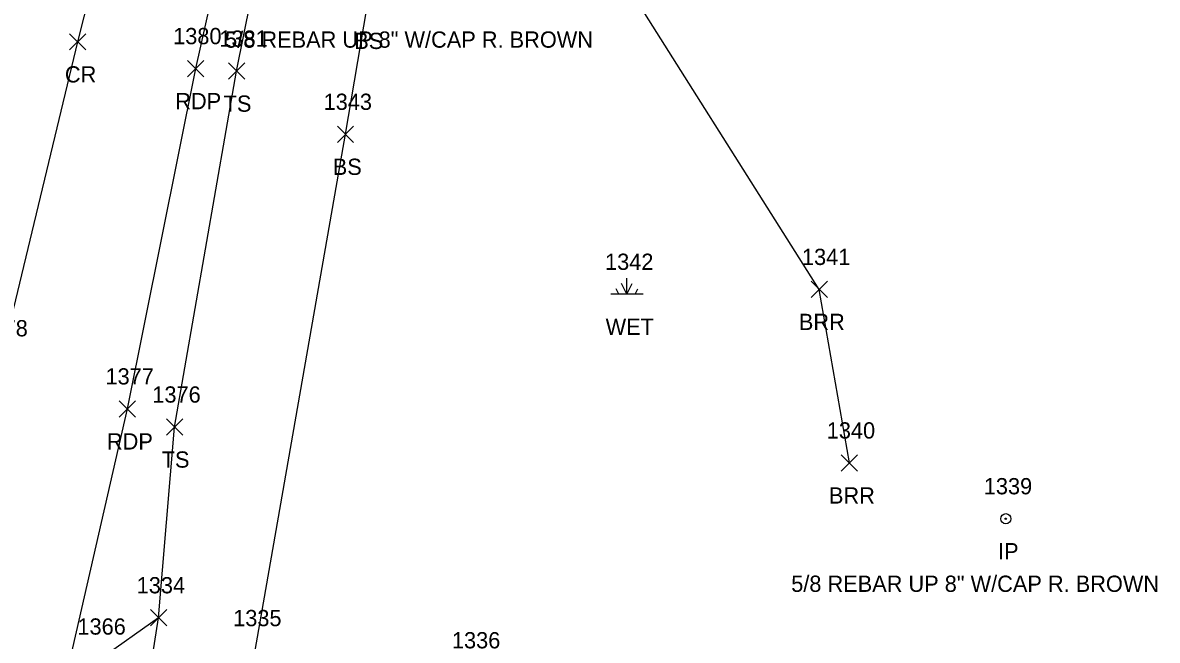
# Model space of a CAD drawing. Extents: x 1654425 to 1656893, y 667839 to 678429.
# Drawn here: x 1654625.8 to 1654765.3, y 668426.8 to 668502.8 of the extents above; entities that cross this region are included whole.
import ezdxf

# ---------------------------------------------------------------- set-up
doc = ezdxf.new("R2010")
doc.units = 0
for name, color, linetype in [('L_A', 7, 'Continuous'), ('L_I', 7, 'Continuous'), ('L_TIC', 7, 'Continuous'), ('LABL', 7, 'Continuous'), ('LELB', 7, 'Continuous'), ('LWET', 7, 'Continuous'), ('M_A', 7, 'Continuous'), ('M_C', 7, 'Continuous'), ('M_I', 7, 'Continuous'), ('MPIR', 7, 'Continuous'), ('P_A', 7, 'Continuous'), ('P_I', 7, 'Continuous'), ('P_TIC', 7, 'Continuous'), ('PET', 7, 'Continuous'), ('PRC', 7, 'Continuous'), ('R_I', 7, 'Continuous'), ('R_TIC', 7, 'Continuous'), ('RGR', 7, 'Continuous')]:
    doc.layers.add(name, color=color, linetype=linetype)

msp = doc.modelspace()

# ---------------------------------------------------------------- linework, layer by layer
at = {"layer": 'L_TIC'}
for points in [[(1654651.12, 668495.86), (1654653.12, 668497.86)], [(1654653.12, 668495.86), (1654651.12, 668497.86)], [(1654664.51, 668488.09), (1654666.51, 668490.09)], [(1654666.51, 668488.09), (1654664.51, 668490.09)], [(1654722.77, 668469.01), (1654724.77, 668471.01)], [(1654724.77, 668469.01), (1654722.77, 668471.01)], [(1654643.5, 668452.08), (1654645.5, 668454.08)], [(1654645.5, 668452.08), (1654643.5, 668454.08)], [(1654726.47, 668447.66), (1654728.47, 668449.66)], [(1654728.47, 668447.66), (1654726.47, 668449.66)], [(1654641.53, 668428.62), (1654643.53, 668430.62)], [(1654643.53, 668428.62), (1654641.53, 668430.62)]]:
    msp.add_lwpolyline(points, dxfattribs=at)
at = {"layer": 'LABL'}
msp.add_lwpolyline([(1654727.47, 668448.66), (1654723.77, 668470.01), (1654697.39, 668511.78), (1654690.89, 668526.25), (1654681.79, 668540.29), (1654676.53, 668550.52), (1654673.89, 668561.81), (1654676.18, 668560.69), (1654702.29, 668559.21), (1654719.79, 668550.09), (1654734.69, 668533.56)], dxfattribs=at)
at = {"layer": 'LELB'}
for points in [[(1654627.02, 668380.04), (1654635.38, 668394.96), (1654638.88, 668406.25), (1654642.53, 668429.62), (1654644.5, 668453.08), (1654652.12, 668496.86), (1654659.06, 668531.43), (1654666.85, 668565.91), (1654678.58, 668597.56)], [(1654632.09, 668378.26), (1654647.7, 668382.66), (1654658.31, 668401.62), (1654653.52, 668410.41), (1654654.39, 668425.58), (1654665.51, 668489.09), (1654668.15, 668504.58), (1654668.74, 668510.32), (1654667.06, 668546.44)]]:
    msp.add_lwpolyline(points, dxfattribs=at)
at = {"layer": 'LWET'}
for p, q in [((1654700.12, 668469.41), (1654699.45, 668470.74)), ((1654700.12, 668469.41), (1654700.12, 668471.41)), ((1654700.12, 668469.41), (1654700.78, 668470.74)), ((1654702.12, 668469.41), (1654698.12, 668469.41)), ((1654699.12, 668469.41), (1654698.78, 668470.08)), ((1654701.12, 668469.41), (1654701.45, 668470.08))]:
    msp.add_line(p, q, dxfattribs=at)
at = {"layer": 'MPIR'}
for radius in [0.625, 0.0833]:
    msp.add_circle((1654746.7, 668441.8), radius, dxfattribs=at)
at = {"layer": 'P_TIC'}
for points in [[(1654631.58, 668499.46), (1654633.58, 668501.46)], [(1654633.58, 668499.46), (1654631.58, 668501.46)], [(1654646.1, 668496.17), (1654648.1, 668498.17)], [(1654648.1, 668496.17), (1654646.1, 668498.17)], [(1654637.69, 668454.31), (1654639.69, 668456.31)], [(1654639.69, 668454.31), (1654637.69, 668456.31)]]:
    msp.add_lwpolyline(points, dxfattribs=at)
at = {"layer": 'PET'}
msp.add_lwpolyline([(1654621.12, 668380.08), (1654629.57, 668415.34), (1654638.69, 668455.31), (1654647.1, 668497.17), (1654655.08, 668532.73), (1654664.14, 668568.47), (1654670.36, 668590.98), (1654672.51, 668598), (1654685.45, 668641.36), (1654697.27, 668678.88), (1654709.65, 668714.91), (1654724.45, 668757.78), (1654737.22, 668795.28), (1654745.33, 668819.59), (1654761.32, 668866.34)], dxfattribs=at)
at = {"layer": 'PRC'}
msp.add_lwpolyline([(1654605.24, 668384.01), (1654612.68, 668416.68), (1654623.19, 668461.23), (1654632.58, 668500.46), (1654641.79, 668536.76), (1654650.75, 668570.78), (1654657.62, 668594.43), (1654672.71, 668645.31)], dxfattribs=at)
at = {"layer": 'R_TIC'}
for points in [[(1654641.53, 668428.62), (1654643.53, 668430.62)], [(1654643.53, 668428.62), (1654641.53, 668430.62)]]:
    msp.add_lwpolyline(points, dxfattribs=at)
at = {"layer": 'RGR'}
msp.add_lwpolyline([(1654642.53, 668429.62), (1654635.35, 668424.54), (1654632.73, 668419.18), (1654625.67, 668394.94), (1654622.06, 668380.67)], dxfattribs=at)

# ---------------------------------------------------------------- texts
at = {"layer": 'L_A'}
for s, p in [('BS', (1654666.59, 668499.58)), ('TS', (1654650.53, 668491.86)), ('BS', (1654663.95, 668484.09)), ('WET', (1654697.5, 668464.41)), ('BRR', (1654721.26, 668465.01)), ('TS', (1654642.91, 668448.08)), ('BRR', (1654724.96, 668443.66))]:
    msp.add_text(s, height=2, dxfattribs=at).set_placement(p)
at = {"layer": 'L_I'}
for s, p in [('1381', (1654650, 668499.86)), ('1343', (1654662.82, 668492.09)), ('1342', (1654697.43, 668472.41)), ('1341', (1654721.64, 668473.01)), ('1376', (1654641.76, 668456.08)), ('1340', (1654724.69, 668451.66)), ('1334', (1654639.84, 668432.62)), ('1335', (1654651.7, 668428.58)), ('1336', (1654678.6, 668425.85))]:
    msp.add_text(s, height=2, dxfattribs=at).set_placement(p)
at = {"layer": 'M_A'}
msp.add_text('IP', height=2, dxfattribs=at).set_placement((1654745.75, 668436.8))
at = {"layer": 'M_C'}
for p in [(1654650.71, 668499.74), (1654720.32, 668432.8)]:
    msp.add_text('5/8 REBAR UP 8" W/CAP R. BROWN', height=2, dxfattribs=at).set_placement(p)
at = {"layer": 'M_I'}
msp.add_text('1339', height=2, dxfattribs=at).set_placement((1654744, 668444.8))
at = {"layer": 'P_A'}
for s, p in [('CR', (1654631.01, 668495.46)), ('RDP', (1654644.58, 668492.17)), ('RDP', (1654636.18, 668450.31))]:
    msp.add_text(s, height=2, dxfattribs=at).set_placement(p)
at = {"layer": 'P_I'}
for s, p in [('1380', (1654644.32, 668500.17)), ('1378', (1654620.5, 668464.23)), ('1377', (1654636, 668458.31))]:
    msp.add_text(s, height=2, dxfattribs=at).set_placement(p)
at = {"layer": 'R_I'}
for s, p in [('1334', (1654639.84, 668432.62)), ('1366', (1654632.55, 668427.54))]:
    msp.add_text(s, height=2, dxfattribs=at).set_placement(p)

doc.saveas('drawing.dxf')
